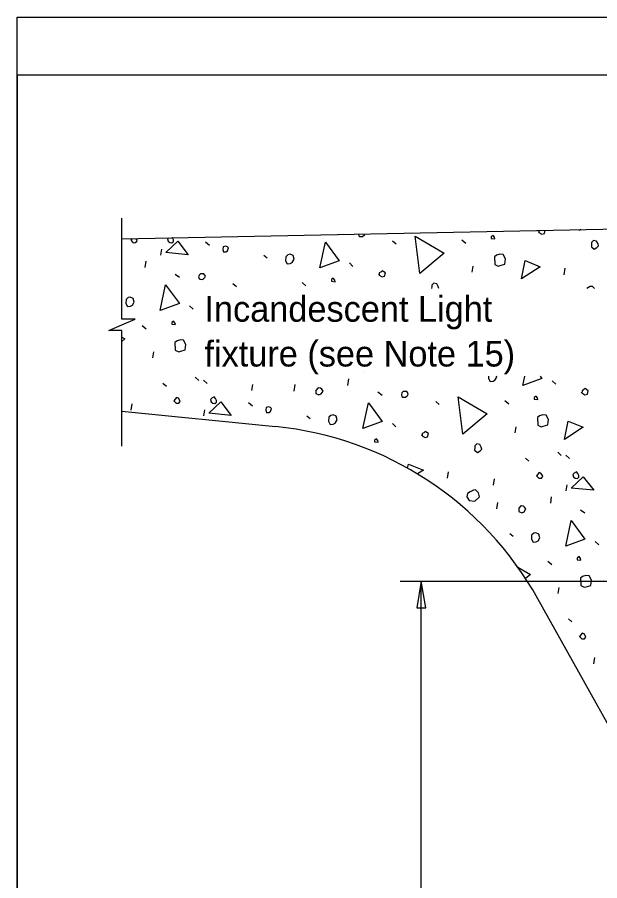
# Model space of a CAD drawing. Extents: x 0 to 30.8, y 0 to 21.2.
# Drawn here: x 0 to 3.43, y 14.71 to 19.8 of the extents above; entities that cross this region are included whole.
import ezdxf

# ---------------------------------------------------------------- set-up
doc = ezdxf.new("R2010")
doc.units = 0
for name, color, linetype in [('ActivePts-ConstElements', 7, 'Continuous'), ('Dimension', 7, 'Continuous'), ('Miscellaneous', 7, 'Continuous'), ('Miscellaneous1', 7, 'Continuous'), ('SupstrConc', 7, 'Continuous')]:
    doc.layers.add(name, color=color, linetype=linetype)

msp = doc.modelspace()

# ---------------------------------------------------------------- linework, layer by layer
at = {"layer": 'ActivePts-ConstElements'}
msp.add_lwpolyline([(0, 0), (30.7879, 0), (30.7879, 19.4596), (0, 19.4596)], close=True, dxfattribs=at)
at = {"layer": 'Dimension'}
for p, q in [((2.2583, 16.4769), (4.1376, 16.4769)), ((2.3818, 10.7741), (2.3818, 16.4769))]:
    msp.add_line(p, q, dxfattribs=at)
msp.add_lwpolyline([(0.6168, 17.2729), (0.6168, 17.9534), (0.5393, 17.9534), (0.6168, 17.9872), (0.6943, 18.0209), (0.6168, 18.0209), (0.6168, 18.6166)], dxfattribs=at)
msp.add_lwpolyline([(2.3818, 16.4768), (2.3553, 16.3206), (2.4082, 16.3206)], close=True, dxfattribs=at)
at = {"layer": 'Miscellaneous'}
for p, q in [((1.1095, 18.4771), (1.1329, 18.4575)), ((1.8968, 18.5208), (1.8978, 18.5201)), ((2.2131, 18.4829), (2.2335, 18.4651)), ((2.6206, 18.4886), (2.6439, 18.4689)), ((0.8459, 18.3987), (0.8519, 18.4339)), ((1.4541, 18.3986), (1.4738, 18.3832)), ((0.7543, 18.325), (0.7597, 18.3627)), ((1.9582, 18.3525), (1.9792, 18.3322)), ((2.682, 18.298), (2.6881, 18.3332)), ((3.2244, 18.2828), (3.2298, 18.3205)), ((0.9302, 18.2867), (0.956, 18.2677)), ((1.2714, 18.2306), (1.2917, 18.2127)), ((1.6788, 18.2362), (1.7022, 18.2166)), ((1.0164, 18.1001), (1.0374, 18.0799)), ((0.737, 17.9839), (0.7604, 17.9642)), ((0.7984, 17.7933), (0.8045, 17.8285)), ((1.049, 17.6792), (1.0699, 17.659)), ((1.0978, 17.6612), (1.1188, 17.641)), ((1.9497, 17.6307), (1.9552, 17.6684)), ((2.0413, 17.7044), (2.0413, 17.7045)), ((3.1536, 17.6582), (3.1746, 17.638)), ((0.8592, 17.6439), (0.8795, 17.626)), ((1.3832, 17.6006), (1.3893, 17.6358)), ((1.6325, 17.5975), (1.638, 17.6352)), ((2.1256, 17.5924), (2.1514, 17.5735)), ((0.6714, 17.4849), (0.6769, 17.5226)), ((1.3632, 17.5305), (1.3866, 17.5109)), ((2.4668, 17.5363), (2.4871, 17.5185)), ((2.8742, 17.5419), (2.8976, 17.5223)), ((1.0995, 17.4521), (1.1056, 17.4873)), ((1.7077, 17.452), (1.7274, 17.4365)), ((2.2119, 17.4059), (2.2328, 17.3856)), ((2.9356, 17.3514), (2.9417, 17.3866)), ((2.9964, 17.202), (3.0167, 17.1841)), ((3.1862, 17.2373), (3.2071, 17.217)), ((3.235, 17.2193), (3.256, 17.1991)), ((2.5363, 17.0839), (2.5417, 17.1216)), ((2.8086, 17.043), (2.8141, 17.0807)), ((3.2367, 17.0101), (3.2428, 17.0454)), ((3.1452, 16.9364), (3.1506, 16.9741)), ((2.828, 16.9032), (2.8334, 16.9409)), ((3.3211, 16.8982), (3.3468, 16.8792)), ((2.9032, 16.7577), (2.9228, 16.7423)), ((3.4073, 16.7116), (3.4282, 16.6914)), ((3.1279, 16.5953), (3.1512, 16.5757)), ((3.1893, 16.4047), (3.1954, 16.44)), ((3.25, 16.2554), (3.2703, 16.2375)), ((3.3988, 15.9898), (3.4042, 16.0275))]:
    msp.add_line(p, q, dxfattribs=at)
for points in [[(2.0114, 18.5231), (2.0112, 18.522), (2.0137, 18.5123)], [(2.0137, 18.5123), (2.0199, 18.5088), (2.0356, 18.5078), (2.0482, 18.519), (2.0499, 18.5238)], [(3.0761, 18.5444), (3.0746, 18.5326), (3.0734, 18.5374)], [(3.0746, 18.5326), (3.093, 18.522), (3.1075, 18.5259), (3.1126, 18.5451)], [(3.3152, 18.5427), (3.3144, 18.5491)], [(3.3233, 18.5493), (3.3152, 18.5427)], [(0.6697, 18.4861), (0.6839, 18.4717), (0.6991, 18.4732), (0.7068, 18.483), (0.7055, 18.4879), (0.6996, 18.4968)], [(0.6779, 18.4964), (0.6775, 18.4959), (0.6697, 18.4861)], [(0.8753, 18.4143), (0.9458, 18.4798), (1.0083, 18.4008), (0.8753, 18.4143)], [(0.8918, 18.5007), (0.8849, 18.4945), (0.8888, 18.48)], [(0.8888, 18.48), (0.8986, 18.4723), (0.912, 18.4707), (0.9203, 18.4781), (0.9202, 18.4885), (0.9145, 18.4999), (0.9136, 18.5011)], [(1.7846, 18.3241), (1.8167, 18.475), (1.898, 18.3648), (1.7846, 18.3241)], [(2.3734, 18.2903), (2.3455, 18.5106), (2.5176, 18.4092), (2.3734, 18.2903)], [(2.7945, 18.4963), (2.8157, 18.4943), (2.8132, 18.5039), (2.8051, 18.5147), (2.7943, 18.5066), (2.7945, 18.4963)], [(3.385, 18.4656), (3.3847, 18.4474), (3.4014, 18.4338), (3.417, 18.4431), (3.4271, 18.4536), (3.4239, 18.4657), (3.4145, 18.4813), (3.3981, 18.4847), (3.3855, 18.4735), (3.385, 18.4656)], [(1.2122, 18.4321), (1.2161, 18.4176), (1.2288, 18.4184), (1.2402, 18.4241), (1.246, 18.4412), (1.2392, 18.4471), (1.2276, 18.4518), (1.2131, 18.4479), (1.2122, 18.4321)], [(1.5834, 18.3892), (1.582, 18.3656), (1.592, 18.3475), (1.6096, 18.3497), (1.621, 18.3553), (1.6316, 18.3737), (1.6258, 18.3954), (1.6081, 18.4036), (1.596, 18.4004), (1.5834, 18.3892)], [(2.8133, 18.3875), (2.8146, 18.3439), (2.8354, 18.3339), (2.8475, 18.3371), (2.8741, 18.3442), (2.8784, 18.3765), (2.864, 18.4011), (2.8452, 18.4038), (2.8258, 18.3986), (2.8133, 18.3875)], [(2.9719, 18.2592), (2.995, 18.3663), (3.0823, 18.3302), (2.9719, 18.2592)], [(1.072, 18.26), (1.0781, 18.2564), (1.0939, 18.2555), (1.1064, 18.2666), (1.1093, 18.2751), (1.1006, 18.2883), (1.08, 18.288), (1.0716, 18.2806), (1.0694, 18.2696), (1.072, 18.26)], [(2.1329, 18.2802), (2.1512, 18.2696), (2.1657, 18.2735), (2.1709, 18.293), (2.1518, 18.306), (2.1435, 18.2986), (2.1345, 18.2936), (2.1329, 18.2802), (2.1316, 18.2851)], [(0.8429, 18.0718), (0.8749, 18.2227), (0.9562, 18.1125), (0.8429, 18.0718)], [(1.8527, 18.244), (1.874, 18.2419), (1.8714, 18.2516), (1.8633, 18.2624), (1.8525, 18.2543), (1.8527, 18.244)], [(2.4852, 18.2018), (2.4821, 18.2133), (2.4727, 18.2289), (2.4563, 18.2323), (2.4437, 18.2212), (2.4433, 18.2133)], [(2.4433, 18.2133), (2.4431, 18.2018)], [(3.403, 18.2018), (3.3905, 18.2135), (3.3778, 18.2126), (3.3573, 18.202), (3.3571, 18.2018)], [(0.6417, 18.1369), (0.6402, 18.1132), (0.6502, 18.0952), (0.6678, 18.0973), (0.6792, 18.103), (0.6898, 18.1213), (0.684, 18.1431), (0.6663, 18.1513), (0.6542, 18.148), (0.6417, 18.1369)], [(0.9109, 17.9916), (0.9322, 17.9896), (0.9296, 17.9992), (0.9215, 18.01), (0.9108, 18.0019), (0.9109, 17.9916)], [(0.6168, 17.9146), (0.634, 17.9045), (0.6168, 17.8903)], [(0.9297, 17.8828), (0.9311, 17.8392), (0.9519, 17.8292), (0.9639, 17.8324), (0.9905, 17.8395), (0.9948, 17.8718), (0.9804, 17.8964), (0.9616, 17.8991), (0.9423, 17.8939), (0.9297, 17.8828)], [(2.7782, 17.6845), (2.7774, 17.6713), (2.7874, 17.6533), (2.805, 17.6554), (2.8164, 17.661), (2.827, 17.6794), (2.8257, 17.6845)], [(2.9801, 17.6298), (2.9917, 17.6845)], [(3.0831, 17.6845), (3.0934, 17.6706), (2.9801, 17.6298)], [(1.761, 17.6008), (1.7607, 17.5826), (1.7785, 17.5745), (1.7923, 17.5808), (1.8036, 17.5967), (1.7955, 17.6075), (1.7887, 17.6134), (1.7778, 17.6157), (1.7729, 17.6144), (1.761, 17.6008)], [(3.3283, 17.586), (3.3467, 17.5754), (3.3611, 17.5792), (3.3663, 17.5987), (3.3473, 17.6118), (3.3389, 17.6043), (3.3299, 17.5993), (3.3283, 17.586), (3.327, 17.5908)], [(0.9234, 17.5395), (0.9376, 17.5251), (0.9527, 17.5266), (0.9604, 17.5364), (0.9591, 17.5413), (0.9504, 17.5545), (0.9388, 17.5591), (0.9311, 17.5493), (0.9234, 17.5395)], [(1.1424, 17.5334), (1.1522, 17.5257), (1.1656, 17.5241), (1.174, 17.5315), (1.1738, 17.5418), (1.1681, 17.5533), (1.1601, 17.5641), (1.1469, 17.5553), (1.1385, 17.5479), (1.1424, 17.5334)], [(2.2674, 17.5657), (2.2735, 17.5622), (2.2893, 17.5612), (2.3018, 17.5723), (2.3047, 17.5809), (2.296, 17.5941), (2.2754, 17.5937), (2.267, 17.5863), (2.2648, 17.5754), (2.2674, 17.5657)], [(2.6271, 17.3437), (2.5991, 17.564), (2.7712, 17.4626), (2.6271, 17.3437)], [(3.0481, 17.5497), (3.0694, 17.5477), (3.0668, 17.5573), (3.0587, 17.5681), (3.0479, 17.56), (3.0481, 17.5497)], [(1.129, 17.4677), (1.1994, 17.5332), (1.262, 17.4542), (1.129, 17.4677)], [(1.4658, 17.4855), (1.4697, 17.471), (1.4824, 17.4718), (1.4939, 17.4775), (1.4996, 17.4946), (1.4929, 17.5005), (1.4813, 17.5052), (1.4668, 17.5013), (1.4658, 17.4855)], [(2.0383, 17.3775), (2.0703, 17.5284), (2.1516, 17.4182), (2.0383, 17.3775)], [(1.8371, 17.4426), (1.8357, 17.419), (1.8457, 17.4009), (1.8632, 17.4031), (1.8746, 17.4087), (1.8852, 17.4271), (1.8794, 17.4488), (1.8617, 17.457), (1.8496, 17.4538), (1.8371, 17.4426)], [(3.0669, 17.4409), (3.0683, 17.3972), (3.0891, 17.3873), (3.1011, 17.3905), (3.1277, 17.3976), (3.132, 17.4299), (3.1176, 17.4545), (3.0988, 17.4572), (3.0795, 17.452), (3.0669, 17.4409)], [(3.2256, 17.3126), (3.2486, 17.4197), (3.3359, 17.3836), (3.2256, 17.3126)], [(2.3865, 17.3336), (2.4049, 17.323), (2.4194, 17.3269), (2.4245, 17.3464), (2.4055, 17.3594), (2.3971, 17.352), (2.3881, 17.347), (2.3865, 17.3336), (2.3852, 17.3385)], [(2.1063, 17.2974), (2.1276, 17.2953), (2.125, 17.305), (2.117, 17.3157), (2.1062, 17.3077), (2.1063, 17.2974)], [(2.6969, 17.2667), (2.6966, 17.2485), (2.7132, 17.2348), (2.7288, 17.2442), (2.739, 17.2547), (2.7357, 17.2667), (2.7264, 17.2823), (2.7099, 17.2857), (2.6974, 17.2746), (2.6969, 17.2667)], [(2.3015, 17.1426), (2.3068, 17.1673), (2.3942, 17.1312), (2.3594, 17.1088)], [(3.0606, 17.0975), (3.0748, 17.0832), (3.0899, 17.0847), (3.0976, 17.0945), (3.0963, 17.0994), (3.0876, 17.1126), (3.076, 17.1172), (3.0683, 17.1074), (3.0606, 17.0975)], [(3.2796, 17.0915), (3.2894, 17.0838), (3.3028, 17.0822), (3.3112, 17.0896), (3.311, 17.0999), (3.3053, 17.1114), (3.2973, 17.1221), (3.2841, 17.1134), (3.2757, 17.106), (3.2796, 17.0915)], [(3.2662, 17.0258), (3.3366, 17.0913), (3.3992, 17.0123), (3.2662, 17.0258)], [(2.6509, 16.9748), (2.6646, 16.9526), (2.6968, 16.9483), (2.7261, 16.9743), (2.7196, 16.9984), (2.7024, 17.0145), (2.6896, 17.0137), (2.6692, 17.003), (2.6536, 16.9937), (2.6509, 16.9748)], [(2.9565, 16.9066), (2.9562, 16.8884), (2.9739, 16.8802), (2.9877, 16.8865), (2.999, 16.9025), (2.9909, 16.9132), (2.9841, 16.9192), (2.9732, 16.9214), (2.9684, 16.9201), (2.9565, 16.9066)], [(3.2337, 16.6832), (3.2657, 16.8342), (3.347, 16.724), (3.2337, 16.6832)], [(3.0325, 16.7484), (3.0311, 16.7247), (3.0411, 16.7067), (3.0586, 16.7088), (3.0701, 16.7144), (3.0807, 16.7328), (3.0748, 16.7545), (3.0571, 16.7627), (3.045, 16.7595), (3.0325, 16.7484)], [(3.3018, 16.6031), (3.323, 16.6011), (3.3204, 16.6107), (3.3124, 16.6215), (3.3016, 16.6134), (3.3018, 16.6031)], [(2.9516, 16.5592), (3.0249, 16.516), (2.9969, 16.4929)], [(3.3206, 16.4943), (3.3219, 16.4506), (3.3427, 16.4407), (3.3548, 16.4439), (3.3813, 16.451), (3.3856, 16.4832), (3.3713, 16.5079), (3.3524, 16.5106), (3.3331, 16.5054), (3.3206, 16.4943)], [(3.3142, 16.1509), (3.3284, 16.1366), (3.3435, 16.1381), (3.3513, 16.1479), (3.35, 16.1527), (3.3413, 16.1659), (3.3297, 16.1706), (3.3219, 16.1608), (3.3142, 16.1509)]]:
    msp.add_lwpolyline(points, dxfattribs=at)
at = {"layer": 'Miscellaneous1'}
msp.add_lwpolyline([(0, 19.8), (30.8, 19.8), (30.8, 0), (0, 0)], close=True, dxfattribs=at)
at = {"layer": 'SupstrConc'}
for p, q in [((0.6169, 18.4952), (10.8054, 18.699)), ((0.6169, 17.4792), (1.5227, 17.3883)), ((6.5193, 10.1908), (3.0695, 16.3729))]:
    msp.add_line(p, q, dxfattribs=at)
msp.add_arc((1.323, 15.3983), 2, 29.163, 84.2698, dxfattribs=at)

# ---------------------------------------------------------------- texts
at = {"layer": 'Dimension'}
for s, p in [('Incandescent Light', (1.1035, 18.0059)), ('fixture (see Note 15)', (1.1035, 17.7419))]:
    msp.add_text(s, height=0.1512, dxfattribs=at).set_placement(p)

doc.saveas('drawing.dxf')
